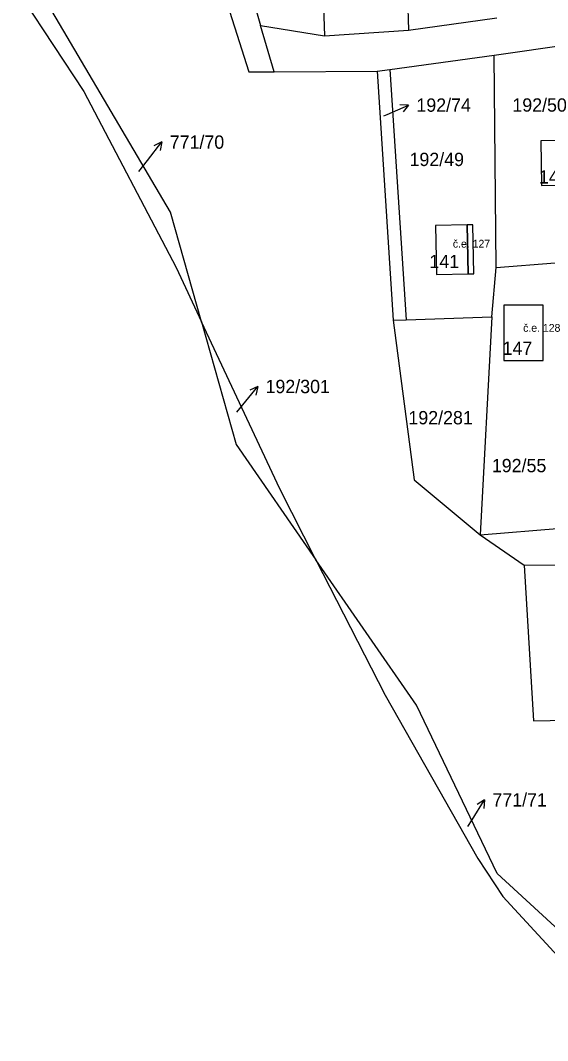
# Model space of a CAD drawing. Extents: x -887272 to -880188, y -1026687 to -1021896.
# Drawn here: x -882525 to -882457.7, y -1024300.5 to -1024170.3 of the extents above; entities that cross this region are included whole.
import ezdxf

# ---------------------------------------------------------------- set-up
doc = ezdxf.new("R2010")
doc.units = 0
for name, color, linetype in [('Definiční body', 7, 'Continuous'), ('Hranice parcel', 7, 'Continuous'), ('Parcelní čísla', 7, 'Continuous'), ('Polygon budovy', 7, 'Continuous'), ('Pop  PČ popisy', 7, 'Continuous'), ('Vnitřní kresba', 7, 'Continuous')]:
    doc.layers.add(name, color=color, linetype=linetype)

msp = doc.modelspace()

# ---------------------------------------------------------------- linework, layer by layer
at = {"layer": 'Hranice parcel'}
for p, q in [((-882487.23, -1024142.35), (-882486.14, -1024172.29)), ((-882476.32, -1024141.77), (-882475.42, -1024171.58)), ((-882494.31, -1024171), (-882486.14, -1024172.29)), ((-882492.56, -1024176.88), (-882494.31, -1024171)), ((-882475.42, -1024171.58), (-882464.13, -1024169.99)), ((-882486.14, -1024172.29), (-882475.42, -1024171.58)), ((-882464.49, -1024174.79), (-882452, -1024172.98)), ((-882477.79, -1024176.61), (-882464.49, -1024174.79)), ((-882464.21, -1024201.86), (-882464.49, -1024174.79)), ((-882492.56, -1024176.88), (-882479.41, -1024176.83)), ((-882479.41, -1024176.83), (-882477.79, -1024176.61)), ((-882479.41, -1024176.83), (-882477.36, -1024208.58)), ((-882477.79, -1024176.61), (-882475.73, -1024208.53)), ((-882464.78, -1024208.18), (-882464.21, -1024201.86)), ((-882464.21, -1024201.86), (-882456.7, -1024201.26)), ((-882477.36, -1024208.58), (-882475.73, -1024208.53)), ((-882475.73, -1024208.53), (-882464.78, -1024208.18)), ((-882464.78, -1024208.18), (-882466.28, -1024236)), ((-882463.24, -1024213.74), (-882458.22, -1024213.73)), ((-882466.28, -1024236), (-882460.64, -1024239.85)), ((-882452.28, -1024239.89), (-882460.64, -1024239.85))]:
    msp.add_line(p, q, dxfattribs=at)
for points in [[(-882497.59, -1024143.48), (-882497.2, -1024160.85), (-882494.31, -1024171)], [(-882501.82, -1024208.81), (-882505.78, -1024194.82), (-882525.14, -1024161.92), (-882540.14, -1024146.21)], [(-882540.14, -1024146.21), (-882538.86, -1024147.89), (-882532.4, -1024155.87), (-882516.84, -1024179.4), (-882505.08, -1024201.85), (-882501.82, -1024208.81)], [(-882514.25, -1024146.09), (-882509.29, -1024158.43), (-882505.52, -1024158.39), (-882501.29, -1024159.64), (-882495.81, -1024176.89), (-882492.56, -1024176.88)], [(-882458.45, -1024191.4), (-882453.75, -1024191.36), (-882453.8, -1024185.66), (-882458.5, -1024185.7), (-882458.45, -1024191.4)], [(-882471.96, -1024196.52), (-882471.84, -1024202.76), (-882467.79, -1024202.68), (-882467.09, -1024202.67), (-882467.19, -1024196.43), (-882467.91, -1024196.44), (-882471.96, -1024196.52)], [(-882458.22, -1024213.73), (-882458.2, -1024206.68), (-882463.25, -1024206.69), (-882463.24, -1024213.74)], [(-882477.36, -1024208.58), (-882474.69, -1024228.97), (-882466.28, -1024236)], [(-882501.82, -1024208.81), (-882497.39, -1024224.47), (-882487.23, -1024239.16)], [(-882487.23, -1024239.16), (-882491.84, -1024230.13), (-882501.82, -1024208.81)], [(-882466.28, -1024236), (-882455.92, -1024235.15), (-882455.98, -1024230.05)], [(-882440.89, -1024300.52), (-882464.08, -1024279.19), (-882474.4, -1024257.7), (-882487.23, -1024239.16)], [(-882487.23, -1024239.16), (-882478.4, -1024256.44), (-882466.55, -1024277.28), (-882463.36, -1024282.12), (-882456.33, -1024289.73), (-882448.49, -1024295.79), (-882440.89, -1024300.52)], [(-882460.64, -1024239.85), (-882459.44, -1024259.7), (-882450.92, -1024259.54)]]:
    msp.add_lwpolyline(points, dxfattribs=at)
at = {"layer": 'Polygon budovy'}
for points in [[(-882458.45, -1024191.4), (-882453.75, -1024191.36), (-882453.8, -1024185.66), (-882458.5, -1024185.7)], [(-882471.84, -1024202.76), (-882467.79, -1024202.68), (-882467.91, -1024196.44), (-882471.96, -1024196.52)], [(-882463.24, -1024213.74), (-882458.22, -1024213.73), (-882458.2, -1024206.68), (-882463.25, -1024206.69)]]:
    msp.add_lwpolyline(points, close=True, dxfattribs=at)
at = {"layer": 'Pop  PČ popisy'}
for p, q in [((-882478.15, -1024182.33), (-882475.39, -1024181.16)), ((-882475.39, -1024181.16), (-882476.51, -1024181.09)), ((-882475.39, -1024181.16), (-882476.11, -1024182.01)), ((-882478.58, -1024182.52), (-882478.15, -1024182.33)), ((-882508.75, -1024188.21), (-882506.9, -1024185.84)), ((-882506.9, -1024185.84), (-882507.91, -1024186.33)), ((-882506.9, -1024185.84), (-882507.12, -1024186.94)), ((-882509.85, -1024189.6), (-882508.75, -1024188.21)), ((-882496.55, -1024219.38), (-882494.66, -1024217.05)), ((-882494.66, -1024217.05), (-882495.68, -1024217.51)), ((-882494.66, -1024217.05), (-882494.9, -1024218.14)), ((-882497.31, -1024220.32), (-882496.55, -1024219.38)), ((-882467.28, -1024272.35), (-882465.69, -1024269.81)), ((-882465.69, -1024269.81), (-882466.65, -1024270.39)), ((-882465.69, -1024269.81), (-882465.8, -1024270.92)), ((-882467.82, -1024273.22), (-882467.28, -1024272.35))]:
    msp.add_line(p, q, dxfattribs=at)
at = {"layer": 'Vnitřní kresba'}
msp.add_line((-882467.91, -1024196.44), (-882467.79, -1024202.68), dxfattribs=at)

# ---------------------------------------------------------------- texts
at = {"layer": 'Definiční body'}
for s, p in [('č.e. 127', (-882469.75, -1024199.33)), ('č.e. 128', (-882460.78, -1024210.07))]:
    msp.add_text(s, height=1, dxfattribs=at).set_placement(p)
at = {"layer": 'Parcelní čísla'}
for s, p in [('192/74', (-882474.4, -1024181.99)), ('192/50', (-882462.15, -1024181.98)), ('771/70', (-882505.89, -1024186.71)), ('192/49', (-882475.28, -1024188.92)), ('142', (-882458.76, -1024191.16)), ('141', (-882472.74, -1024201.95)), ('147', (-882463.4, -1024213.01)), ('192/301', (-882493.66, -1024217.9)), ('192/281', (-882475.42, -1024221.88)), ('192/55', (-882464.77, -1024227.99)), ('771/71', (-882464.7, -1024270.65))]:
    msp.add_text(s, height=1.7, dxfattribs=at).set_placement(p)

doc.saveas('drawing.dxf')
